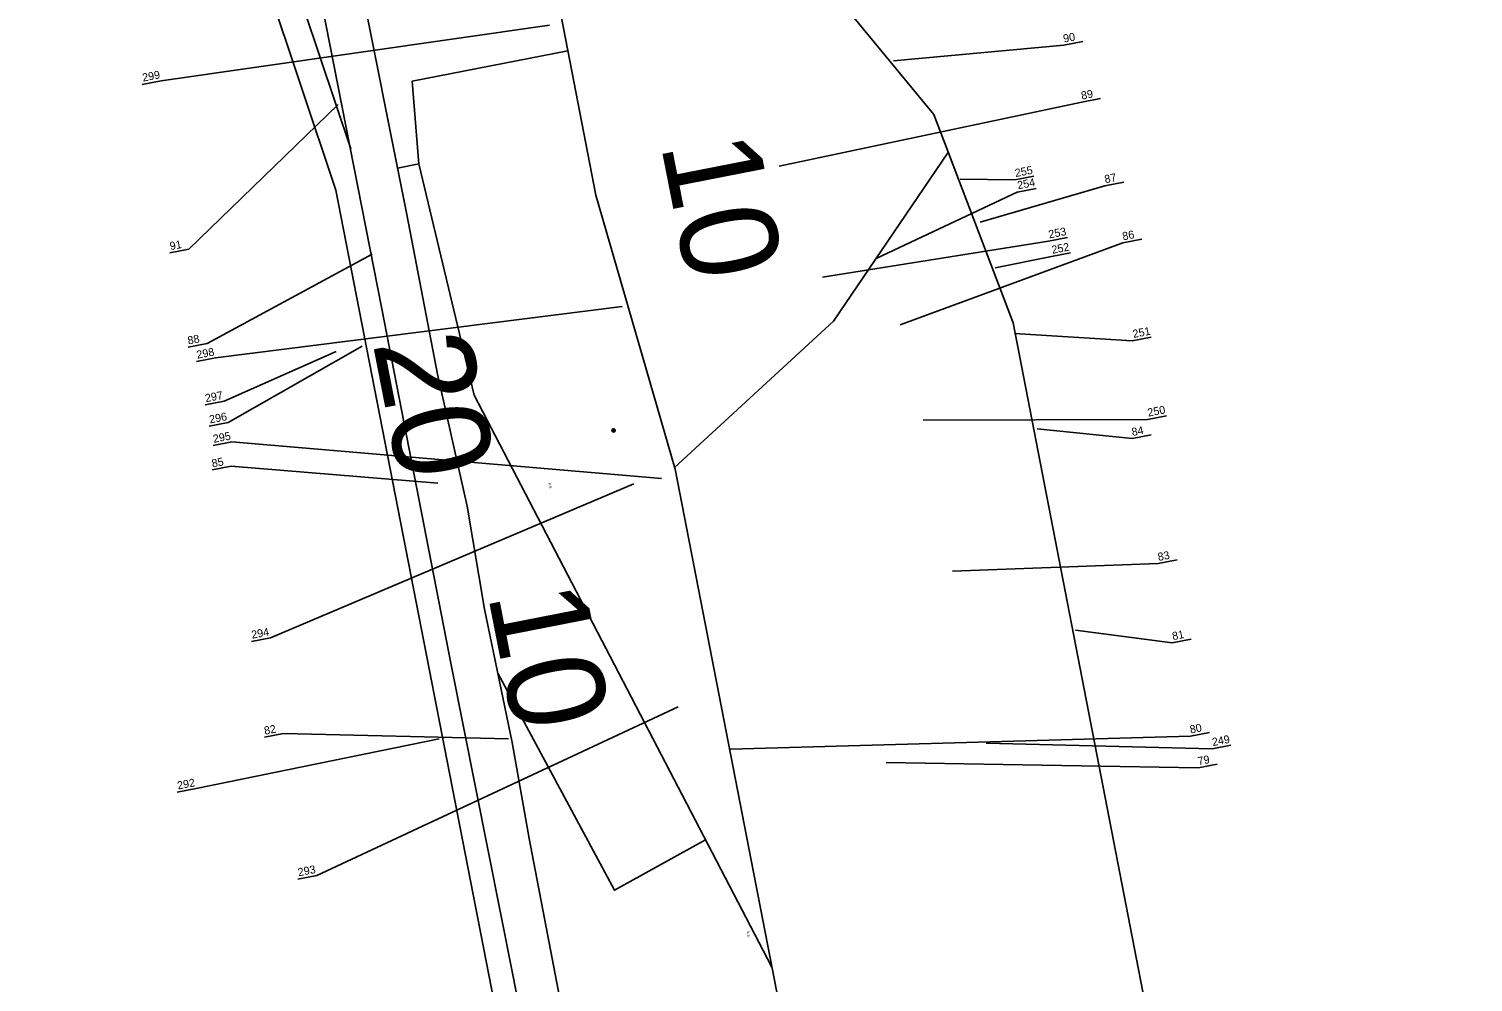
# Model space of a CAD drawing. Extents: x -545967 to -545044, y -1122650 to -1118491.
# Drawn here: x -545736.2 to -545397.9, y -1119701.2 to -1119477.8 of the extents above; entities that cross this region are included whole.
import ezdxf

# ---------------------------------------------------------------- set-up
doc = ezdxf.new("R2010")
doc.units = 0
for name, color, linetype in [('osvětlené plochy-hodnota-obrys', 7, 'Continuous'), ('so180602', 7, 'Continuous'), ('Vrstva 63', 7, 'Continuous')]:
    doc.layers.add(name, color=color, linetype=linetype)

msp = doc.modelspace()

# ---------------------------------------------------------------- linework, layer by layer
at = {"layer": 'osvětlené plochy-hodnota-obrys'}
msp.add_line((-545562.16, -1119697.71), (-545631.88, -1119563.68), dxfattribs=at)
for points in [[(-545664.28, -1119515.64), (-545680.45, -1119467.23), (-545736.2, -1119180.74), (-545730.57, -1119179.65)], [(-545730.57, -1119179.65), (-545675.35, -1119462.61), (-545660.82, -1119505.94)], [(-545716.39, -1119223.72), (-545705.99, -1119221.66), (-545669.44, -1119408.76), (-545659.4, -1119462.63), (-545647.69, -1119521.35), (-545640.52, -1119558.73), (-545633.58, -1119589.7), (-545629.52, -1119613.81), (-545623.04, -1119645.06), (-545619.03, -1119667.56), (-545607.52, -1119727.52)], [(-545610.9, -1119760.66), (-545622.84, -1119699.49), (-545637.26, -1119626.87), (-545653.54, -1119543.45), (-545716.39, -1119223.72)], [(-545610.46, -1119381.57), (-545587.49, -1119421.11), (-545524.22, -1119497.93), (-545520.97, -1119506.47)], [(-545584.85, -1119581.02), (-545603.39, -1119516.8), (-545628.87, -1119385.18)], [(-545609.94, -1119482.98), (-545646.43, -1119490.11), (-545644.9, -1119509.52)], [(-545520.97, -1119506.47), (-545505.64, -1119546.72), (-545397.93, -1120102.85)], [(-545649.85, -1119510.5), (-545644.88, -1119509.51), (-545631.88, -1119563.68)], [(-545520.95, -1119506.89), (-545547.77, -1119546.31), (-545584.96, -1119580.66)], [(-545618.79, -1119749.17), (-545664.28, -1119515.64)], [(-545441.66, -1120319.91), (-545444.67, -1120302.28), (-545584.85, -1119581.02)], [(-545577.74, -1119667.87), (-545599.03, -1119679.69), (-545626.4, -1119628.8)]]:
    msp.add_lwpolyline(points, dxfattribs=at)
at = {"layer": 'Vrstva 63'}
for p, q in [((-545614.24, -1119476.95), (-545705.2, -1119490)), ((-545493.81, -1119481.66), (-545533.65, -1119485.32)), ((-545489.37, -1119480.79), (-545493.81, -1119481.66)), ((-545705.2, -1119490), (-545709.64, -1119490.86)), ((-545663.75, -1119495.57), (-545698.77, -1119529.46)), ((-545489.61, -1119495.02), (-545560.47, -1119510)), ((-545485.17, -1119494.16), (-545489.61, -1119495.02)), ((-545505.25, -1119513.21), (-545518.1, -1119513.06)), ((-545500.81, -1119512.35), (-545505.25, -1119513.21)), ((-545500.81, -1119512.35), (-545505.25, -1119513.21)), ((-545500.81, -1119512.35), (-545505.25, -1119513.21)), ((-545504.69, -1119516.08), (-545537.6, -1119531.59)), ((-545484.16, -1119514.61), (-545513.35, -1119523.17)), ((-545500.25, -1119515.22), (-545504.69, -1119516.08)), ((-545500.25, -1119515.22), (-545504.69, -1119516.08)), ((-545500.25, -1119515.22), (-545504.69, -1119516.08)), ((-545479.71, -1119513.75), (-545484.16, -1119514.61)), ((-545492.94, -1119526.72), (-545497.38, -1119527.58)), ((-545492.94, -1119526.72), (-545497.38, -1119527.58)), ((-545492.94, -1119526.72), (-545497.38, -1119527.58)), ((-545698.77, -1119529.46), (-545703.21, -1119530.32)), ((-545497.38, -1119527.58), (-545550.35, -1119536.06)), ((-545479.95, -1119527.98), (-545532.1, -1119547.23)), ((-545492.23, -1119530.34), (-545496.67, -1119531.21)), ((-545492.23, -1119530.34), (-545496.67, -1119531.21)), ((-545492.23, -1119530.34), (-545496.67, -1119531.21)), ((-545475.51, -1119527.11), (-545479.95, -1119527.98)), ((-545655.76, -1119530.65), (-545694.44, -1119551.55)), ((-545496.67, -1119531.21), (-545509.91, -1119533.81)), ((-545597.23, -1119542.92), (-545692.49, -1119554.94)), ((-545477.79, -1119550.96), (-545505.33, -1119549.21)), ((-545473.35, -1119550.09), (-545477.79, -1119550.96)), ((-545473.35, -1119550.09), (-545477.79, -1119550.96)), ((-545473.35, -1119550.09), (-545477.79, -1119550.96)), ((-545694.44, -1119551.55), (-545698.89, -1119552.41)), ((-545664.24, -1119553.46), (-545690.49, -1119565.12)), ((-545658.1, -1119552.23), (-545689.52, -1119570.1)), ((-545692.49, -1119554.94), (-545696.93, -1119555.8)), ((-545690.49, -1119565.12), (-545694.94, -1119565.98)), ((-545689.52, -1119570.1), (-545693.96, -1119570.96)), ((-545474.19, -1119569.36), (-545526.76, -1119569.55)), ((-545469.75, -1119568.5), (-545474.19, -1119569.36)), ((-545469.75, -1119568.5), (-545474.19, -1119569.36)), ((-545469.75, -1119568.5), (-545474.19, -1119569.36)), ((-545599.64, -1119571.99), (-545599.44, -1119571.78)), ((-545599.59, -1119572.15), (-545599.33, -1119571.89)), ((-545599.53, -1119572.23), (-545598.99, -1119571.68)), ((-545599.53, -1119571.69), (-545599.26, -1119571.96)), ((-545599.53, -1119571.69), (-545598.99, -1119572.23)), ((-545599.26, -1119571.96), (-545599.53, -1119572.23)), ((-545599.26, -1119571.96), (-545599.53, -1119572.23)), ((-545599.26, -1119571.96), (-545598.99, -1119571.68)), ((-545599.26, -1119571.96), (-545598.99, -1119572.23)), ((-545598.99, -1119572.23), (-545599.26, -1119571.96)), ((-545599.19, -1119572.03), (-545598.93, -1119571.77)), ((-545599.08, -1119572.14), (-545598.88, -1119571.93)), ((-545477.78, -1119573.85), (-545500.07, -1119571.55)), ((-545473.34, -1119572.98), (-545477.78, -1119573.85)), ((-545688.63, -1119574.64), (-545693.07, -1119575.51)), ((-545588.03, -1119583.24), (-545688.63, -1119574.64)), ((-545688.81, -1119580.35), (-545693.25, -1119581.21)), ((-545640.39, -1119584.28), (-545688.81, -1119580.35)), ((-545594.49, -1119584.44), (-545679.64, -1119620.55)), ((-545471.67, -1119603.12), (-545519.87, -1119604.96)), ((-545467.22, -1119602.26), (-545471.67, -1119603.12)), ((-545679.64, -1119620.55), (-545684.09, -1119621.42)), ((-545468.42, -1119621.71), (-545491.06, -1119618.73)), ((-545463.97, -1119620.84), (-545468.42, -1119621.71)), ((-545584.14, -1119636.74), (-545668.75, -1119676.21)), ((-545640.09, -1119644.23), (-545697.01, -1119655.88)), ((-545676.55, -1119642.97), (-545681, -1119643.83)), ((-545623.89, -1119644.19), (-545676.55, -1119642.97)), ((-545464.14, -1119643.56), (-545571.89, -1119646.62)), ((-545459.08, -1119646.57), (-545512.02, -1119645.22)), ((-545459.69, -1119642.7), (-545464.14, -1119643.56)), ((-545454.64, -1119645.7), (-545459.08, -1119646.57)), ((-545454.64, -1119645.7), (-545459.08, -1119646.57)), ((-545454.64, -1119645.7), (-545459.08, -1119646.57)), ((-545462.3, -1119650.98), (-545535.41, -1119649.74)), ((-545457.86, -1119650.12), (-545462.3, -1119650.98)), ((-545697.01, -1119655.88), (-545701.46, -1119656.75)), ((-545668.75, -1119676.21), (-545673.2, -1119677.07))]:
    msp.add_line(p, q, dxfattribs=at)
msp.add_circle((-545599.26, -1119571.96), 0.382, dxfattribs=at)
for radius, start, end in [(0.382, 134.523, 224.841), (0.383, 315.2118, 45.1053)]:
    msp.add_arc((-545599.26, -1119571.96), radius, start, end, dxfattribs=at)

# ---------------------------------------------------------------- texts
at = {"layer": 'osvětlené plochy-hodnota-obrys'}
for s, p in [('10', (-545588.24, -1119504.87)), ('20', (-545655.7, -1119551.44)), ('10', (-545628.76, -1119610.29))]:
    msp.add_text(s, height=22.781, rotation=281.0956, dxfattribs=at).set_placement(p)
at = {"layer": 'so180602'}
for s, p in [('90', (-545493.75, -1119481.07)), ('299', (-545709.45, -1119490.22)), ('89', (-545489.55, -1119494.44)), ('255', (-545505.06, -1119512.58)), ('254', (-545504.5, -1119515.45)), ('87', (-545484.08, -1119514.03)), ('253', (-545497.19, -1119526.95)), ('86', (-545479.89, -1119527.4)), ('91', (-545703.01, -1119529.71)), ('252', (-545496.47, -1119530.57)), ('88', (-545698.83, -1119551.83)), ('251', (-545477.47, -1119550.29)), ('298', (-545696.74, -1119555.17)), ('297', (-545694.74, -1119565.34)), ('250', (-545474, -1119568.73)), ('296', (-545693.77, -1119570.32)), ('84', (-545477.72, -1119573.27)), ('295', (-545692.88, -1119574.87)), ('85', (-545693.19, -1119580.63)), ('83', (-545471.61, -1119602.54)), ('294', (-545683.9, -1119620.78)), ('81', (-545468.22, -1119621.1)), ('82', (-545680.92, -1119643.25)), ('80', (-545464.08, -1119642.98)), ('249', (-545458.89, -1119645.93)), ('79', (-545462.24, -1119650.4)), ('292', (-545701.26, -1119656.11)), ('293', (-545673.01, -1119676.44))]:
    msp.add_text(s, height=1.875, rotation=10.9955, dxfattribs=at).set_placement(p)
at = {"layer": 'Vrstva 63'}
for height, rotation, p in [(0.695, 286.4026, (-545614.57, -1119584.35)), (0.688, 279.922, (-545568.06, -1119689.4))]:
    msp.add_text('k.s.', height=height, rotation=rotation, dxfattribs=at).set_placement(p)

doc.saveas('drawing.dxf')
